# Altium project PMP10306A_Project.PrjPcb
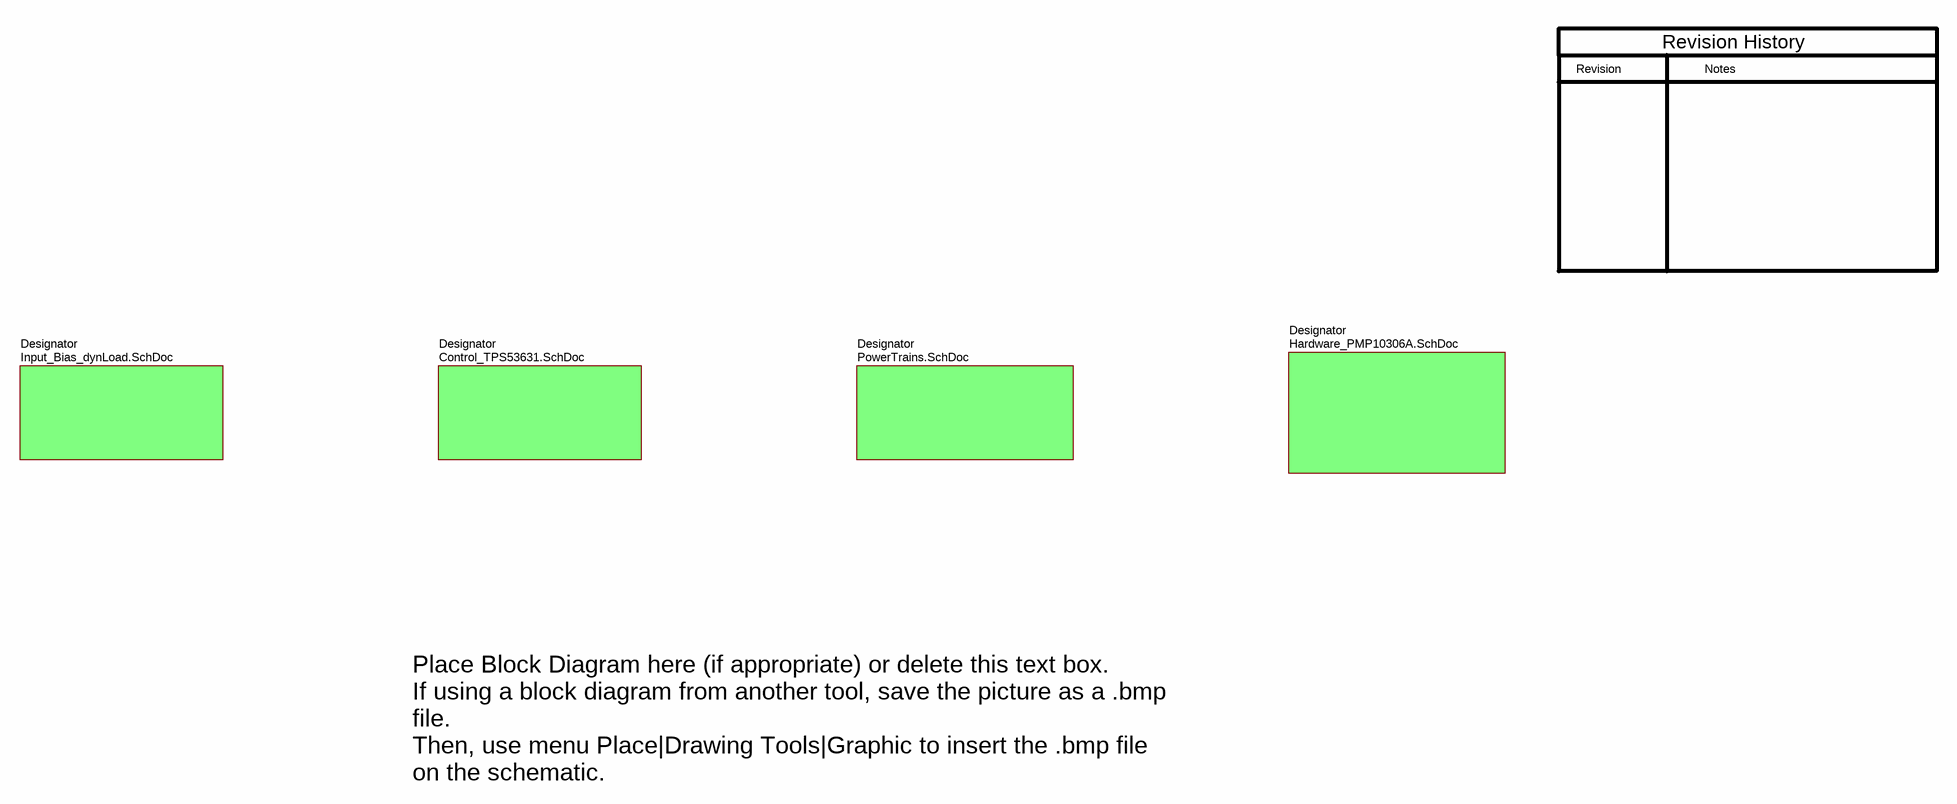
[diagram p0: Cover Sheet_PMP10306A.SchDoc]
TechSupport: http://www.ti.com/support; SCH_Rev: A; PRJ_Title: TPS53631 / CSD95378B(x3) for DDR4; PRJ_Number: PMP10306; PRJ_Engineer: Josh Mandelcorn; PRJ_Customer: Public Release; PCB_Rev: A; PCB_Layout: Use PMP9738A PCB; CopyrightYear: 2014
5 sheets, 207 parts. Net scope: flat (ports and power ports of the same name join across sheets).
Board file: PMP10306A.PcbDoc
Sheets:
  Cover Sheet_PMP10306A.SchDoc
    Designator = Input_Bias_dynLoad.SchDoc
    Designator = Control_TPS53631.SchDoc
    Designator = PowerTrains.SchDoc
    Designator = Hardware_PMP10306A.SchDoc

## Sheet Cover Sheet_PMP10306A.SchDoc
size 431 x 279 mm; Date: Not shown in title block; ApprovedBy: Not shown in title block; CheckedBy: Not shown in title block; Author: Not shown in title block; CompanyName: Not shown in title block; Engineer: Not shown in title block; Organization: Not shown in title block; Address1: Not shown in title block; Address2: Not shown in title block; Address3: Not shown in title block; Address4: Not shown in title block; DocumentNumber: 1; Revision: Use project parameter SCH_Rev; SheetNumber: 1; SheetTotal: 5; PageSetup: Record=PageOptions|CenterHorizontal=True|CenterVertical=True|PrintScale=1.00|XCorrection=1.00|YCorrection=1.00|PrintKind=0|BorderSize=5000000|LeftOffset=0|BottomOffset=0|Orientation=2|PaperLength=1000|PaperWidth=1000|Scale=100|PaperSource=15|PrintQuality=600|MediaType=1|DitherType=10|PaperKind=Letter|PrintScaleMode=1

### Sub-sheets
Designator = Input_Bias_dynLoad.SchDoc: no entries
Designator = Control_TPS53631.SchDoc: no entries
Designator = PowerTrains.SchDoc: no entries
Designator = Hardware_PMP10306A.SchDoc: no entries

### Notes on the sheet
- Revision
- Notes
- Revision History
- Place Block Diagram here (if appropriate) or delete this text box.
  If using a block diagram from another tool, save the picture as a .bmp file.
  Then, use menu Place|Drawing Tools|Graphic to insert the .bmp file on the schematic.

## Sheet Input_Bias_dynLoad.SchDoc
size 431 x 279 mm; Date: Not shown in title block; ApprovedBy: Not shown in title block; CheckedBy: Not shown in title block; Author: Not shown in title block; CompanyName: Not shown in title block; Engineer: Not shown in title block; Organization: Not shown in title block; Address1: Not shown in title block; Address2: Not shown in title block; Address3: Not shown in title block; Address4: Not shown in title block; DocumentNumber: 2; Revision: Use project parameter SCH_Rev; SheetNumber: 2; SheetTotal: 5; PageSetup: Record=PageOptions|CenterHorizontal=True|CenterVertical=True|PrintScale=1.00|XCorrection=1.00|YCorrection=1.00|PrintKind=0|BorderSize=5000000|LeftOffset=0|BottomOffset=0|Orientation=2|PaperLength=1000|PaperWidth=1000|Scale=100|PaperSource=15|PrintQuality=600|MediaType=1|DitherType=10|PaperKind=Letter|PrintScaleMode=1
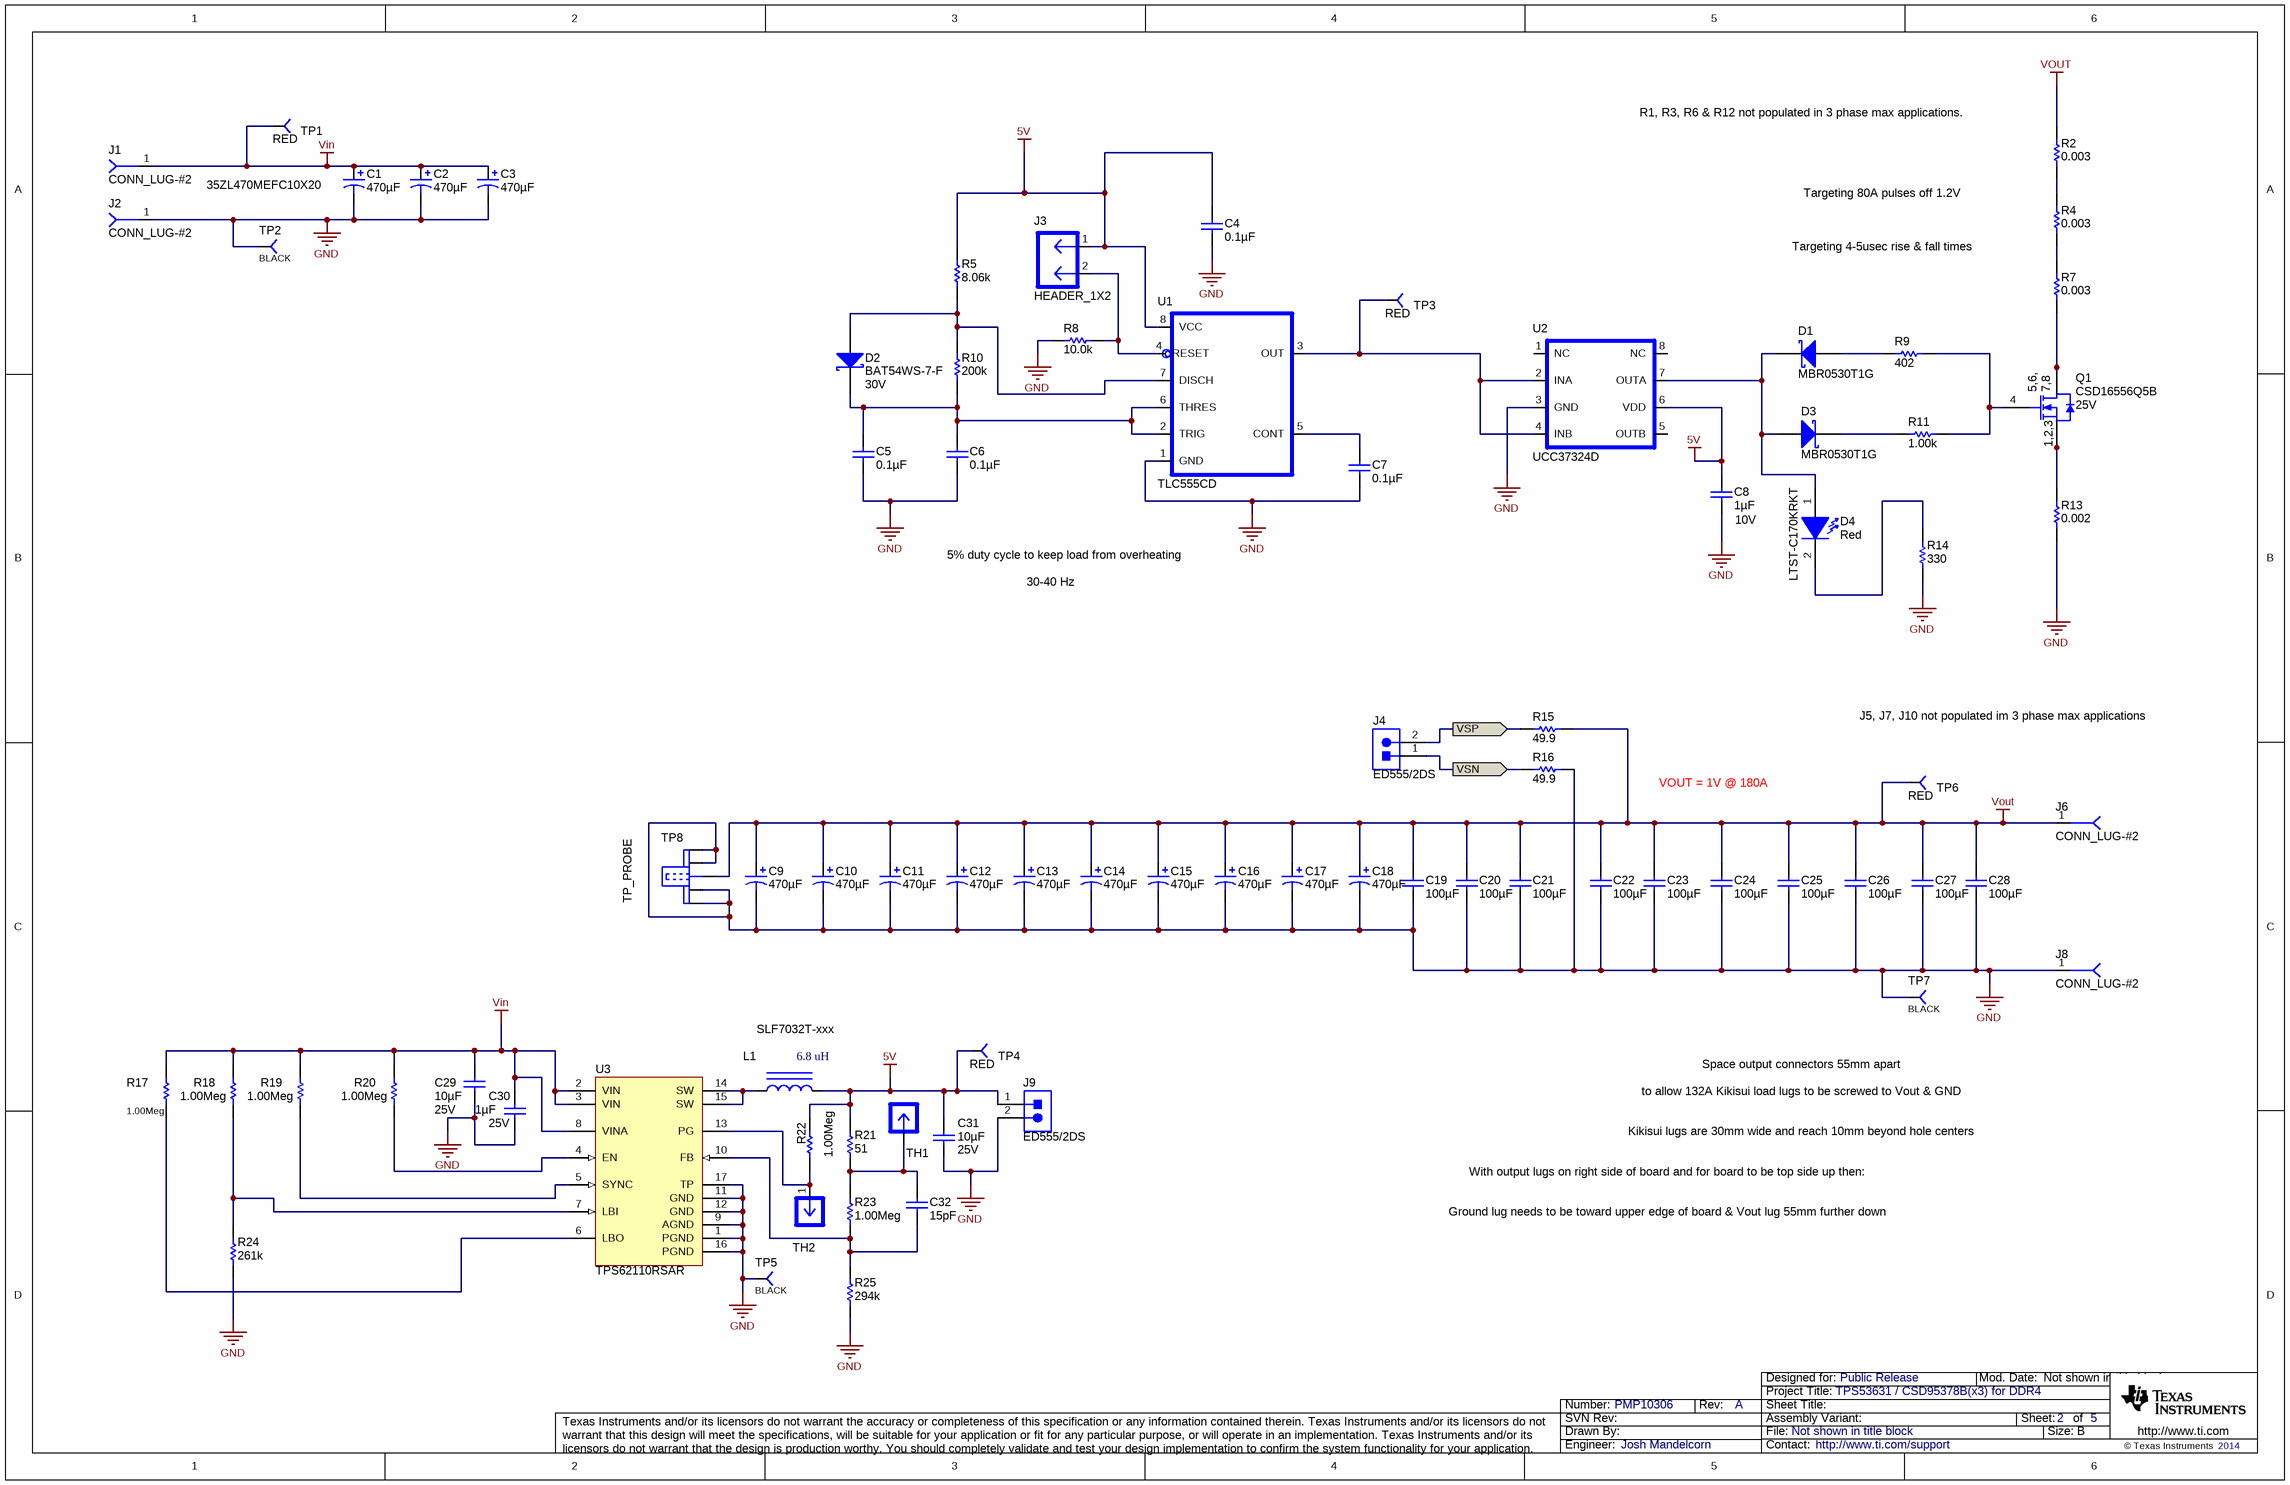
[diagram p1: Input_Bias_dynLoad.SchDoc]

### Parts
C1  ValueDisplayed: 470µF  [CAPPR5-10X20]  (hidden comment: 35ZL470MEFC10X20)
C2  ValueDisplayed: 470µF  [CAPPR5-10X20]  (hidden comment: 35ZL470MEFC10X20)
C3  ValueDisplayed: 470µF  [CAPPR5-10X20]  (hidden comment: 35ZL470MEFC10X20)
C4  ValueDisplayed: 0.1µF  [0402]  (hidden comment: C1005X7R1H104M)
C5  ValueDisplayed: 0.1µF  [0402]  (hidden comment: C1005X7R1H104M)
C6  ValueDisplayed: 0.1µF  [0402]  (hidden comment: C1005X7R1H104M)
C7  ValueDisplayed: 0.1µF  [0402]  (hidden comment: C1005X7R1H104M)
C8  ValueDisplayed: 1µF  Value2: 10V  [0402]  (hidden comment: GRM155R61A105KE15D)
C9  ValueDisplayed: 470µF  [CAPAE_SP-Cap_Standard]  (hidden comment: EEFSX0E471ER)
C10  ValueDisplayed: 470µF  [CAPAE_SP-Cap_Standard]  (hidden comment: EEFSX0E471ER)
C11  ValueDisplayed: 470µF  [CAPAE_SP-Cap_Standard]  (hidden comment: EEFSX0E471ER)
C12  ValueDisplayed: 470µF  [CAPAE_SP-Cap_Standard]  (hidden comment: EEFSX0E471ER)
C13  ValueDisplayed: 470µF  [CAPAE_SP-Cap_Standard]  (hidden comment: EEFSX0E471ER)
C14  ValueDisplayed: 470µF  [CAPAE_SP-Cap_Standard]  (hidden comment: EEFSX0E471ER)
C15  ValueDisplayed: 470µF  [CAPAE_SP-Cap_Standard]  (hidden comment: EEFSX0E471ER)
C16  ValueDisplayed: 470µF  [CAPAE_SP-Cap_Standard]  (hidden comment: EEFSX0E471ER)
C17  ValueDisplayed: 470µF  [CAPAE_SP-Cap_Standard]  (hidden comment: EEFSX0E471ER)
C18  ValueDisplayed: 470µF  [CAPAE_SP-Cap_Standard]  (hidden comment: EEFSX0E471ER)
C19  ValueDisplayed: 100µF  [1210]  (hidden comment: C1210C107M9PACTU)
C20  ValueDisplayed: 100µF  [1210]  (hidden comment: C1210C107M9PACTU)
C21  ValueDisplayed: 100µF  [1210]  (hidden comment: C1210C107M9PACTU)
C22  ValueDisplayed: 100µF  [1210]  (hidden comment: C1210C107M9PACTU)
C23  ValueDisplayed: 100µF  [1210]  (hidden comment: C1210C107M9PACTU)
C24  ValueDisplayed: 100µF  [1210]  (hidden comment: C1210C107M9PACTU)
C25  ValueDisplayed: 100µF  [1210]  (hidden comment: C1210C107M9PACTU)
C26  ValueDisplayed: 100µF  [1210]  (hidden comment: C1210C107M9PACTU)
C27  ValueDisplayed: 100µF  [1210]  (hidden comment: C1210C107M9PACTU)
C28  ValueDisplayed: 100µF  [1210]  (hidden comment: C1210C107M9PACTU)
C29  ValueDisplayed: 10µF  Value2: 25V  [1210]  (hidden comment: C3225X7R1E106M)
C30  ValueDisplayed: 1µF  Value2: 25V  [0603]  (hidden comment: GRM188R71E105KA12D)
C31  ValueDisplayed: 10µF  Value2: 25V  [1210]  (hidden comment: C3225X7R1E106M)
C32  ValueDisplayed: 15pF  [0402]  (hidden comment: GRM1555C1H150JA01D)
D1  MBR0530T1G  [SOD-123]
D2  BAT54WS-7-F  value 30V  [sod-323]
D3  MBR0530T1G  [SOD-123]
D4  LTST-C170KRKT  value Red  [LED_LTST-C170]
J1  CONN_LUG-#2  [LUG-#2]
J2  CONN_LUG-#2  [LUG-#2]
J3  HEADER_1X2  [HDR100_1X2]
J4  ED555/2DS  [TERM_BLK_ED555-2DS]
J6  CONN_LUG-#2  [LUG-#2]
J8  CONN_LUG-#2  [LUG-#2]
J9  ED555/2DS  [TERM_BLK_ED555-2DS]
L1  SLF7032T-xxx  value 6.8 uH  [IND_SLF7032]
Q1  CSD16556Q5B  value 25V  [TRANS_NexFET_Q5B]
R2  value 0.003  [2512M]  (hidden comment: 73M1R003F)
R4  value 0.003  [2512M]  (hidden comment: 73M1R003F)
R5  value 8.06k  [0402]  (hidden comment: CRCW04028K06FKED)
R7  value 0.003  [2512M]  (hidden comment: 73M1R003F)
R8  value 10.0k  [0402]  (hidden comment: CRCW040210K0FKED)
R9  value 402  [0402]  (hidden comment: CRCW0402402RFKED)
R10  value 200k  [0402]  (hidden comment: CRCW0402200KFKED)
R11  value 1.00k  [0402]  (hidden comment: CRCW04021K00FKED)
R13  value 0.002  [2512M]  (hidden comment: CSNL2512FT2L00)
R14  value 330  [0402]  (hidden comment: CRCW0402330RJNED)
R15  value 49.9  [0402]  (hidden comment: CRCW040249R9FKED)
R16  value 49.9  [0402]  (hidden comment: CRCW040249R9FKED)
R17  value 1.00Meg  [0402]  (hidden comment: CRCW04021M00FKED)
R18  value 1.00Meg  [0402]  (hidden comment: CRCW04021M00FKED)
R19  value 1.00Meg  [0402]  (hidden comment: CRCW04021M00FKED)
R20  value 1.00Meg  [0402]  (hidden comment: CRCW04021M00FKED)
R21  value 51  [0402]  (hidden comment: CRCW040251R0JNED)
R22  value 1.00Meg  [0402]  (hidden comment: CRCW04021M00FKED)
R23  value 1.00Meg  [0402]  (hidden comment: CRCW04021M00FKED)
R24  value 261k  [0402]  (hidden comment: CRCW0402261KFKED)
R25  value 294k  [0402]  (hidden comment: CRCW0402294KFKED)
TH1  TP-15MIL  [TH-15MIL]  (value not drawn)
TH2  TP-15MIL  [TH-15MIL]  (value not drawn)
TP1  RED  [TH-40]
TP2  BLACK  [TH-40]
TP3  RED  [TH-40]
TP4  RED  [TH-40]
TP5  BLACK  [TH-40]
TP6  RED  [TH-40]
TP7  BLACK  [TH-40]
TP8  TP_PROBE  [PROBE]
U1  TLC555CD  [SO8]
U2  UCC37324D  [SO8]
U3  TPS62110RSAR  [RSA0016B]

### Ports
VSN (out), VSP (out)

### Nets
5V: C4.1 C8.1 C31.1 J3.1 J9.1 L1.2 R5.2 R21.2 R22.2 TP4.1 U1.8(VCC) U2.6(VDD)
GND: C1.2(-) C2.2(-) C3.2(-) C4.2 C5.2 C6.2 C7.2 C8.2 C9.2(-) C10.2(-) C11.2(-) C12.2(-) C13.2(-) C14.2(-) C15.2(-) C16.2(-) C17.2(-) C18.2(-) C19.2 C20.2 C21.2 C22.2 C23.2 C24.2 C25.2 C26.2 C27.2 C28.2 C29.2 C30.2 C31.2 J2.1 J8.1 J9.2 R8.1 R13.1 R14.1 R16.2 R24.1 R25.1 TP2.1 TP5.1 TP7.1 TP8.2(GND) TP8.3(GND) TP8.4(GND) TP8.5(GND) U1.1(GND) U2.3(GND) U3.1(PGND) U3.9(AGND) U3.11(GND) U3.12(GND) U3.16(PGND) U3.17(TP)
Vin: C1.1(+) C2.1(+) C3.1(+) C29.1 C30.1 J1.1 R17.2 R18.2 R19.1 R20.2 TP1.1 U3.2(VIN) U3.3(VIN) U3.8(VINA)
VOUT: C9.1(+) C10.1(+) C11.1(+) C12.1(+) C13.1(+) C14.1(+) C15.1(+) C16.1(+) C17.1(+) C18.1(+) C19.1 C20.1 C21.1 C22.1 C23.1 C24.1 C25.1 C26.1 C27.1 C28.1 J6.1 R2.2 R15.2 TP6.1 TP8.1(SIGNAL)
VSN: J4.1 R16.1 ; port VSN
VSP: J4.2 R15.1 ; port VSP
NetC5_1: C5.1 C6.1 D2.1(K) R10.1 U1.2(TRIG) U1.6(THRES)
NetC7_1: C7.1 U1.5(CONT)
NetC32_1: C32.1 R21.1 R23.2 TH1.1
NetC32_2: C32.2 R23.1 R25.2 U3.10(FB)
NetD1_1: D1.1(K) D3.2(A) D4.1(A) U2.7(OUTA)
NetD1_2: D1.2(A) R9.1
NetD2_2: D2.2(A) R5.1 R10.2 U1.7(DISCH)
NetD3_1: D3.1(K) R11.1
NetD4_2: D4.2(K) R14.2
NetJ3_2: J3.2 R8.2 U1.4(RESET)
NetL1_1: L1.1 U3.14(SW) U3.15(SW)
NetQ1_1: Q1.1(S) Q1.2(S) Q1.3(S) R13.2
NetQ1_4: Q1.4(G) R9.2 R11.2
NetQ1_5: Q1.5(D) Q1.6(D) Q1.7(D) Q1.8(D) R7.1
NetR2_1: R2.1 R4.2
NetR4_1: R4.1 R7.2
NetR17_1: R17.1 U3.6(LBO)
NetR18_1: R18.1 R24.2 U3.7(LBI)
NetR19_2: R19.2 U3.5(SYNC)
NetR20_1: R20.1 U3.4(EN)
NetR22_1: R22.1 TH2.1 U3.13(PG)
NetTP3_1: TP3.1 U1.3(OUT) U2.2(INA) U2.4(INB)

Not connected (* = marked no-connect by the designer): U2 1(NC) 5(OUTB) 8(NC)

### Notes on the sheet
- R1, R3, R6 & R12 not populated in 3 phase max applications.
- Targeting 80A pulses off 1.2V
- Targeting 4-5usec rise & fall times
- 5% duty cycle to keep load from overheating
- 30-40 Hz
- J5, J7, J10 not populated im 3 phase max applications
- VOUT = 1V @ 180A
- Space output connectors 55mm apart
- to allow 132A Kikisui load lugs to be screwed to Vout & GND
- With output lugs on right side of board and for board to be top side up then:
- Kikisui lugs are 30mm wide and reach 10mm beyond hole centers
- Ground lug needs to be toward upper edge of board & Vout lug 55mm further down

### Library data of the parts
C1-C3 = 35ZL470MEFC10X20: CAP, AL, 470uF, 35V, +/-20%, TH; Manufacturer: Rubycon; Polarized: Y; CompType: Capacitor; U/M: EA; Cap_F: 0.00047; Tolerance_%: 20; Value1: Unknown; VDC_V: 35; TaMin_C: -40; TaMax_C: 105; Cap_Case: 10x20
C4-C7 = C1005X7R1H104M: CAP, CERM, 0.1uF, 50V, +/-20%, X7R, 0402; Manufacturer: TDK; Polarized: N; CompType: Capacitor; U/M: EA; Cap_F: 0.0000001; Tolerance_%: 20; Value1: Unknown; VDC_V: 50; TempCo: C0G/NP0; TaMin_C: -55; TaMax_C: 125
C8 = GRM155R61A105KE15D: CAP, CERM, 1uF, 10V, +/-10%, X5R, 0402; Manufacturer: MuRata; Polarized: N; CompType: Capacitor; U/M: EA; Cap_F: 0.000001; Tolerance_%: 10; Value1: Unknown; TaMin_C: -55; TaMax_C: 85
C9-C18 = EEFSX0E471ER: CAP, AL, 470uF, 2.5V, +/-20%, 9 ohm, SMD; Manufacturer: Panasonic; Polarized: Y; CompType: Capacitor; U/M: EA; Cap_F: 0.00047; Tolerance_%: 20; Value1: 9 ohm; VDC_V: 2.5; ESR_Ohm: 9; IRMS_A: 3; TaMin_C: -40; TaMax_C: 105
C19-C28 = C1210C107M9PACTU: CAP, CERM, 100uF, 6.3V, +/-20%, X5R, 1210; Manufacturer: Kemet; Polarized: N; CompType: Capacitor; U/M: EA; Cap_F: 0.0001; Tolerance_%: 20; Value1: Unknown; VDC_V: 6.3; TaMin_C: -55; TaMax_C: 85
C29 C31 = C3225X7R1E106M: CAP, CERM, 10uF, 25V, +/-20%, X7R, 1210; Manufacturer: TDK; Polarized: N; CompType: Capacitor; U/M: EA; Cap_F: 0.00001; Tolerance_%: 20; ESR_Ohm: 0.0027; Value1: 0.0027 ohm; VDC_V: 25; IRMS_A: 3; TaMin_C: -55; TaMax_C: 125
C30 = GRM188R71E105KA12D: CAP, CERM, 1uF, 25V, +/-10%, X7R, 0603; Manufacturer: MuRata; Polarized: N; CompType: Capacitor; U/M: EA; Cap_F: 0.000001; Tolerance_%: 10; Value1: Unknown; VDC_V: 25; TaMin_C: -55; TaMax_C: 125
C32 = GRM1555C1H150JA01D: CAP, CERM, 15pF, 50V, +/-5%, C0G/NP0, 0402; Manufacturer: MuRata; Polarized: N; CompType: Capacitor; U/M: EA; Cap_F: 0.000000000015; Tolerance_%: 5; Value1: Unknown; VDC_V: 50; TaMin_C: -55; TaMax_C: 125
D1 D3 = MBR0530T1G: Diode, Schottky, 30V, 0.5A, SOD-123; Manufacturer: ON Semiconductor; U/M: EA; Vf_V: 0.43; Value2: 0.43V; Io_A: 0.5; Vr_V: 30; TJmax_C: 125; RJC_CperW: 150
D2 = BAT54WS-7-F: Diode, Schottky, 30V, 0.2A, SOD-323; Manufacturer: Diodes Inc.; U/M: EA; Vf_V: 0.7; Value2: 0.7V; Io_A: 0.2; Vr_V: 30; TJmax_C: 125
D4 = LTST-C170KRKT: LED, Red, SMD; Manufacturer: Lite-On; Type: AlInGaP; Vf_V: 2; Value2: 2V; Io_A: 20; Value1: W; U/M: EA
J1 J2 J6 J8 = CONN_LUG-#2: Lug, Solderless, #2 - #8 AWG, 1/4", Copper; Manufacturer: ILSCO; PartNumber: GSLU-70; area: 960000; Value: GSLU-70
J3 = HEADER_1X2: Header, Male 2-pin, 100mil spacing,; Manufacturer: Sullins; PartNumber: PEC02SAAN; area: 20000; Value: PEC02SAAN
J4 J9 = ED555/2DS: Terminal Block, 6A, 3.5mm Pitch, 2-Pos, TH; Manufacturer: On-Shore Technology; SymbolCreator: a0412235; CompType: Connector; U/M: EA
L1 = IND_SLF7032T-XXX: Inductor, SMT, yyA, zzmilliohm; Manufacturer: TDK; Area: 114,138
Q1 = CSD16556Q5B: MOSFET, N-CH, 25V, 40A, SON 5x6mm; Manufacturer: Texas Instruments; Alternate Manufacturer: None; U/M: EA; ChType: N; VdsMax_V: 25; Value1: 0.0012 ohm; Rdson45_Ohm: 0.0012; Value2: 36 nC; QgTyp_nC: 36; Vgs_V: 20; IdsMax_A: 40
R2 R4 R7 = 73M1R003F: RES, 0.003 ohm, 1%, 1W, 2512; Manufacturer: CTS Resistor; CompType: Resistor; Value_Code: R003; Tolerance_%: 1; TempCo: 300 ppm/C; EIA_Code: E96; U/M: EA
R5 = CRCW04028K06FKED: RES, 8.06k ohm, 1%, 0.063W, 0402; Manufacturer: Vishay-Dale; CompType: Resistor; Res_ohm: 8060; Value_Code: 8k06; Tolerance_%: 1; Power_W: 0.063; VDC_V: 50; TempCo: 100 ppm/C; EIA_Code: E96; U/M: EA
R8 = CRCW040210K0FKED: RES, 10.0k ohm, 1%, 0.063W, 0402; Manufacturer: Vishay-Dale; CompType: Resistor; Res_ohm: 10000; Value_Code: 10k0; Tolerance_%: 1; Power_W: 0.063; VDC_V: 50; TempCo: 100 ppm/C; EIA_Code: E96; U/M: EA
R9 = CRCW0402402RFKED: RES, 402 ohm, 1%, 0.063W, 0402; Manufacturer: Vishay-Dale; CompType: Resistor; Value_Code: 402R; Tolerance_%: 1; Power_W: 0.063; VDC_V: 50; TempCo: 100 ppm/C; EIA_Code: E96; U/M: EA
R10 = CRCW0402200KFKED: RES, 200k ohm, 1%, 0.063W, 0402; Manufacturer: Vishay-Dale; CompType: Resistor; Res_ohm: 200000; Tolerance_%: 1; Power_W: 0.063; VDC_V: 50; TempCo: 100 ppm/C; EIA_Code: E96; U/M: EA
R11 = CRCW04021K00FKED: RES, 1.00k ohm, 1%, 0.063W, 0402; Manufacturer: Vishay-Dale; CompType: Resistor; Res_ohm: 1000; Value_Code: 1k00; Tolerance_%: 1; Power_W: 0.063; VDC_V: 50; TempCo: 100 ppm/C; EIA_Code: E96; U/M: EA
R13 = CSNL2512FT2L00: RES, 0.002 ohm, 1%, 2W, 2512; Manufacturer: Stackpole Electronics Inc; CompType: Resistor; Value_Code: R002; Tolerance_%: 1; Power_W: 2; VDC_V: 200; TempCo: 50 ppm/C; U/M: EA
R14 = CRCW0402330RJNED: RES, 330 ohm, 5%, 0.063W, 0402; Manufacturer: Vishay-Dale; CompType: Resistor; Value_Code: 330R; Tolerance_%: 5; Power_W: 0.063; VDC_V: 50; TempCo: 200 ppm/C; EIA_Code: E24; U/M: EA
R15 R16 = CRCW040249R9FKED: RES, 49.9 ohm, 1%, 0.063W, 0402; Manufacturer: Vishay-Dale; CompType: Resistor; Value_Code: 49R9; Tolerance_%: 1; Power_W: 0.063; VDC_V: 50; TempCo: 100 ppm/C; EIA_Code: E96; U/M: EA
R17-R20 R22 R23 = CRCW04021M00FKED: RES, 1.00Meg ohm, 1%, 0.063W, 0402; Manufacturer: Vishay-Dale; CompType: Resistor; Res_ohm: 1000000; Value_Code: 1M00; Tolerance_%: 1; Power_W: 0.063; VDC_V: 50; TempCo: 100 ppm/C; EIA_Code: E96; U/M: EA
R21 = CRCW040251R0JNED: RES, 51 ohm, 5%, 0.063W, 0402; Manufacturer: Vishay-Dale; CompType: Resistor; Value_Code: 51R0; Tolerance_%: 5; Power_W: 0.063; VDC_V: 50; TempCo: 200 ppm/C; EIA_Code: E24; U/M: EA
R24 = CRCW0402261KFKED: RES, 261k ohm, 1%, 0.063W, 0402; Manufacturer: Vishay-Dale; CompType: Resistor; Res_ohm: 261000; Tolerance_%: 1; Power_W: 0.063; VDC_V: 50; TempCo: 100 ppm/C; EIA_Code: E96; U/M: EA
R25 = CRCW0402294KFKED: RES, 294k ohm, 1%, 0.063W, 0402; Manufacturer: Vishay-Dale; CompType: Resistor; Res_ohm: 294000; Tolerance_%: 1; Power_W: 0.063; VDC_V: 50; TempCo: 100 ppm/C; EIA_Code: E96; U/M: EA
TH1 TH2 = TP-15MIL: Thru Hole, 15 mil, plated
TP1 TP3 TP4 TP6 = TP-5000-RED: Test Point,  Red, Thru Hole Color Keyed; Manufacturer: Keystone; PartNumber: 5000; area: 10.000; Value: 5000
TP2 TP5 TP7 = TP-5001-BLACK: Test Point,  Black, Thru Hole Color Keyed; Manufacturer: Keystone; PartNumber: 5001; area: 10.000; Value: 5001
TP8 = TP_PROBE: Adaptor, 3.5-mm probe clip (or 131-5031-00); Manufacturer: Tektronix; PartNumber: 131-4244-00; Value: 131-4244-00
U1 = TLC555CD: IC, Timer, Low-Power CMOS; Manufacturer: TI; Alternate Manufacturer: None; Area: 75900
U2 = UCC3732XD: IC, Dual  4-A High Speed Low-Side Power MOSFET Drivers; Manufacturer: TI; Alternate Manufacturer: None; Area: 75900
U3 = TPS62110RSAR: Buck Adjustable Regulator with 3.1 to 17 V Input and 1.2 to 16 V Output, -40 to 85 degC, 16-Pin QFN (RSA), Green (RoHS & no Sb/Br); Manufacturer: Texas Instruments; Alternate Manufacturer: None; Alternate PartNumber: Equivalent; Duty Cycle(Max)(%): 100; Iout(Max)(A): 1.5; Iq(Typ)(mA): 0.02; Rating: Catalog; Regulated Outputs(#): 1; SubFamily: Step-Down Regulator; Switch Current Limit(Typ)(A): 2.4; Synchronous Rectification: TRUE; Vin(Max)(V): 17; Vin(Min)(V): 3.1; Vout(Max)(V): 16; Vout(Min)(V): 1.2

## Sheet Control_TPS53631.SchDoc
size 431 x 279 mm; Date: Not shown in title block; ApprovedBy: Not shown in title block; CheckedBy: Not shown in title block; Author: Not shown in title block; CompanyName: Not shown in title block; Engineer: Not shown in title block; Organization: Not shown in title block; Address1: Not shown in title block; Address2: Not shown in title block; Address3: Not shown in title block; Address4: Not shown in title block; DocumentNumber: 3; Revision: Use project parameter SCH_Rev; SheetNumber: 3; SheetTotal: 5; PageSetup: Record=PageOptions|CenterHorizontal=True|CenterVertical=True|PrintScale=1.00|XCorrection=1.00|YCorrection=1.00|PrintKind=0|BorderSize=5000000|LeftOffset=0|BottomOffset=0|Orientation=2|PaperLength=1000|PaperWidth=1000|Scale=100|PaperSource=15|PrintQuality=600|MediaType=1|DitherType=10|PaperKind=Letter|PrintScaleMode=1
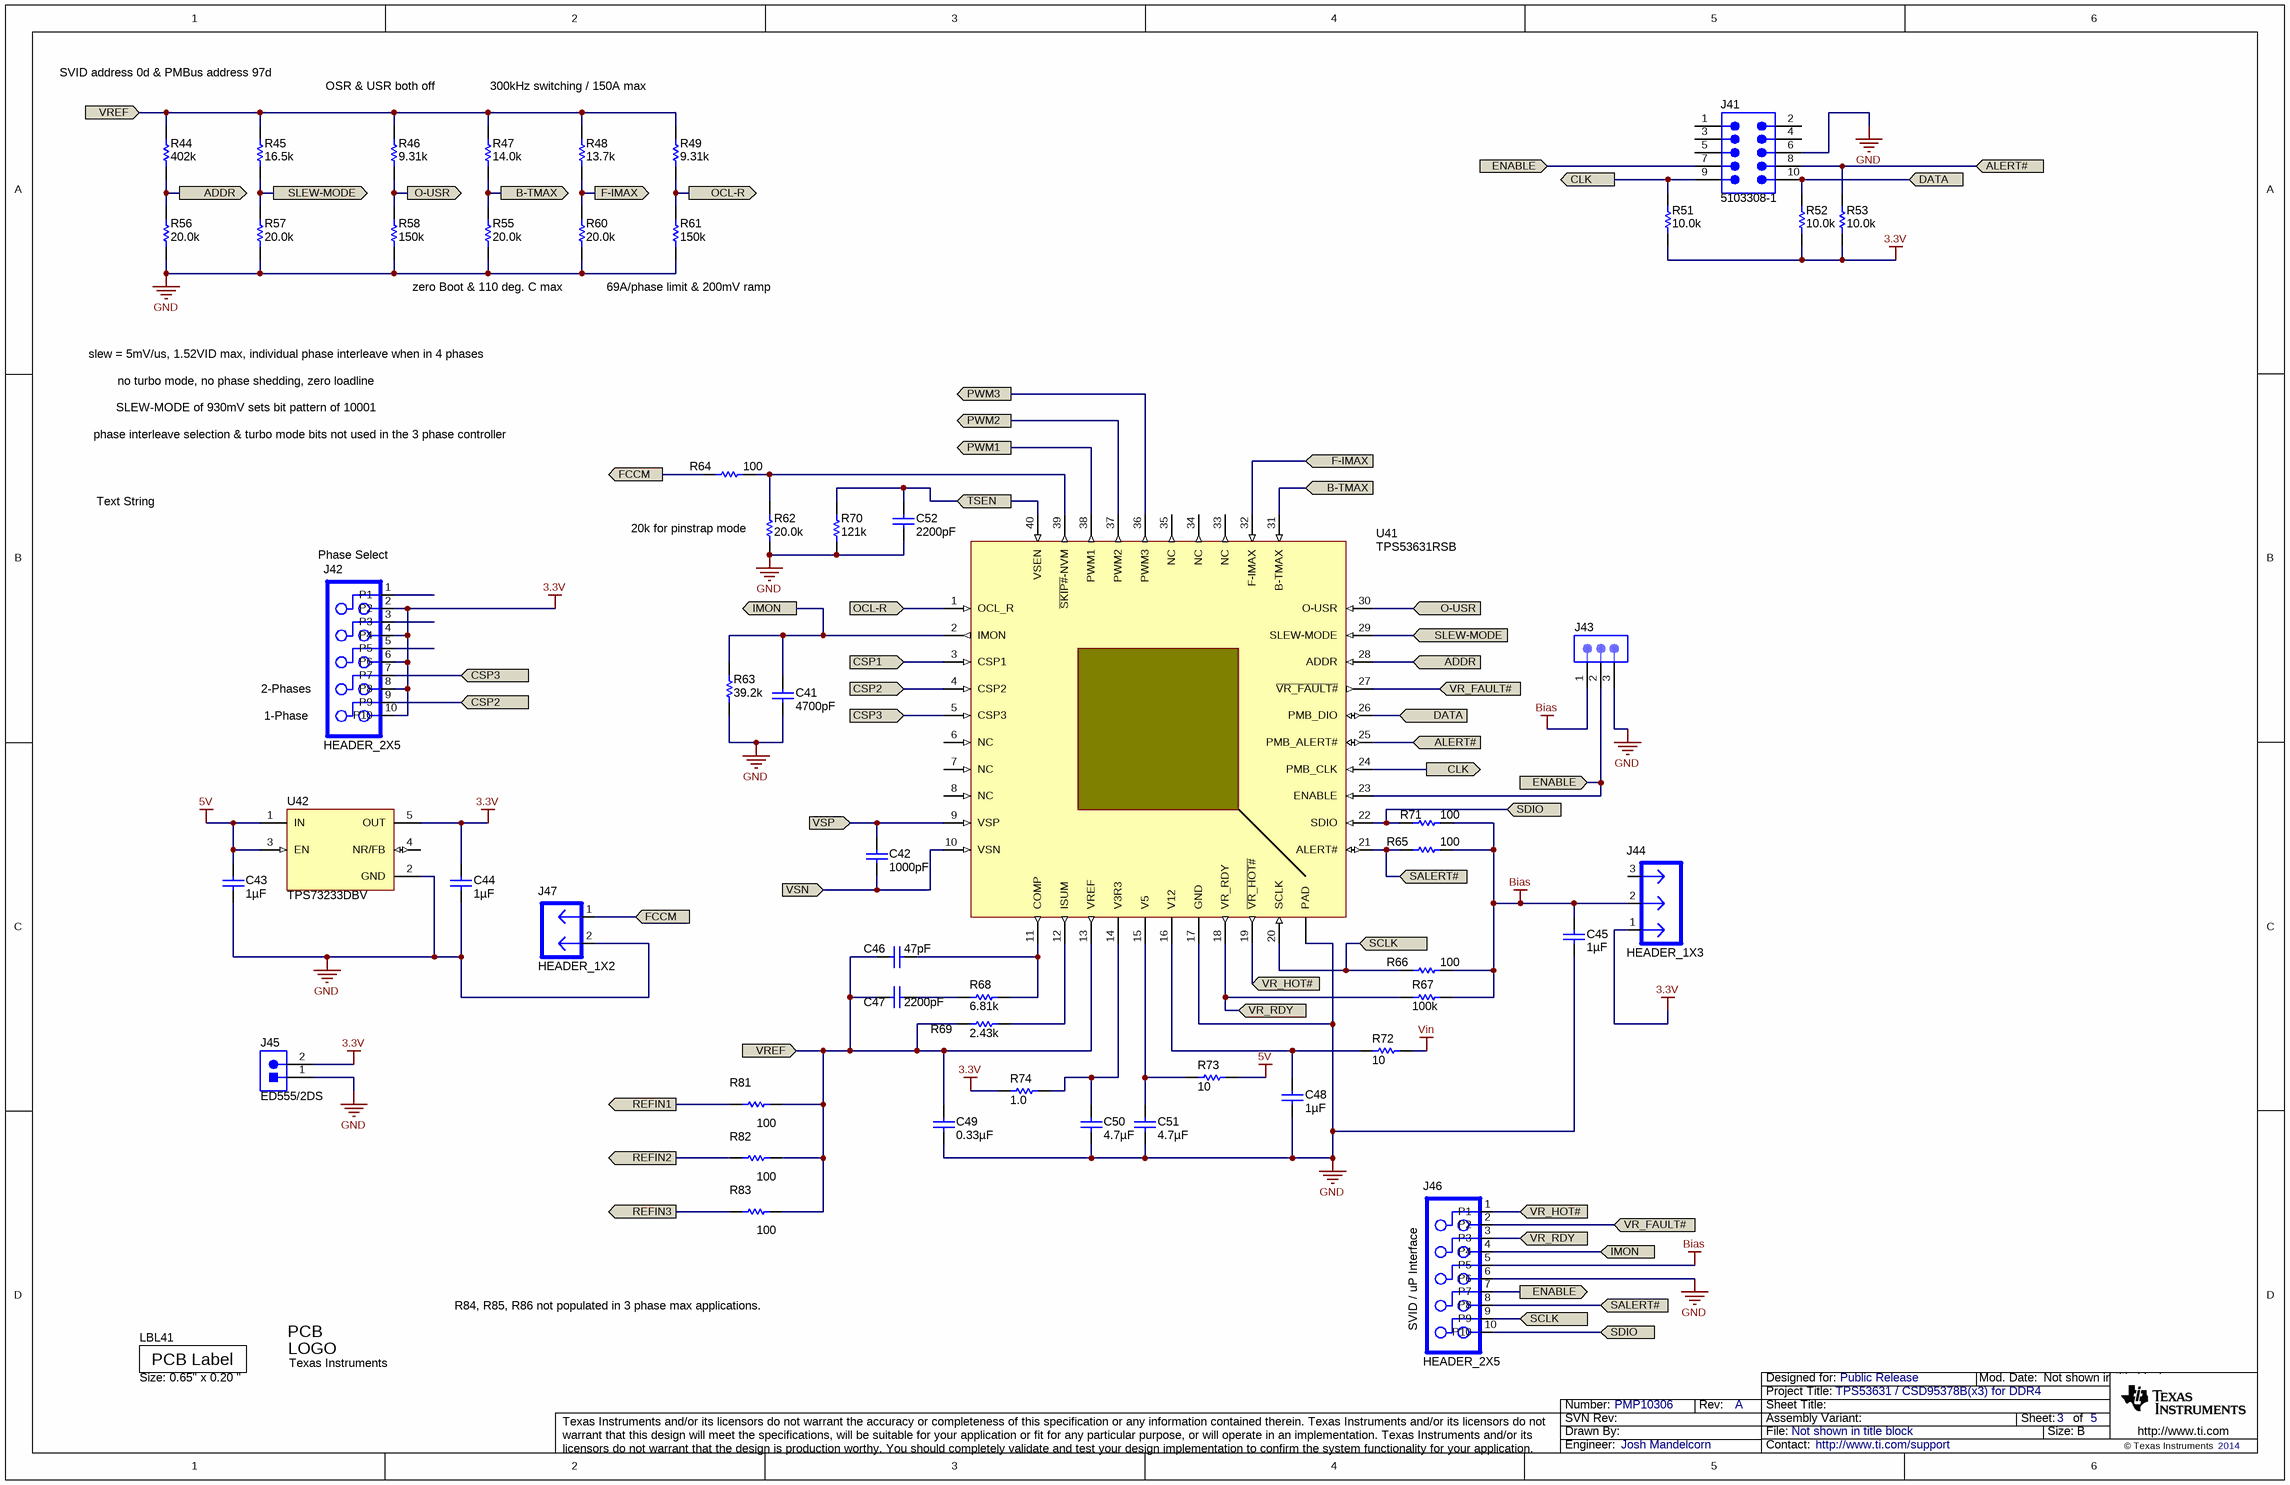
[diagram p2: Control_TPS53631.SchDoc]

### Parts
C41  ValueDisplayed: 4700pF  [0603]  (hidden comment: 06031C472KAT2A)
C42  ValueDisplayed: 1000pF  [0402]  (hidden comment: C1005X7R1H102K)
C43  ValueDisplayed: 1µF  [0603]  (hidden comment: C1608X5R1E105K080AC)
C44  ValueDisplayed: 1µF  [0603]  (hidden comment: C1608X5R1E105K080AC)
C45  ValueDisplayed: 1µF  [0603]  (hidden comment: C1608X5R1E105K080AC)
C46  ValueDisplayed: 47pF  [0402]  (hidden comment: GRM1555C1H470JA01D)
C47  ValueDisplayed: 2200pF  [0603]  (hidden comment: GRM188R71H222KA01D)
C48  ValueDisplayed: 1µF  [0603]  (hidden comment: C1608X5R1E105K080AC)
C49  ValueDisplayed: 0.33µF  [0402]  (hidden comment: GRM155R60J334KE01D)
C50  ValueDisplayed: 4.7µF  [0402]  (hidden comment: GRM155R61A475M)
C51  ValueDisplayed: 4.7µF  [0402]  (hidden comment: GRM155R61A475M)
C52  ValueDisplayed: 2200pF  [0402]  (hidden comment: C1005X7R1H222K)
J41  5103308-1  [CONN_5103308-1]
J42  HEADER_2X5  [HEADER_2X5]
J43  PBC03SAAN  [PBC03SAAN]  (value not drawn)
J44  HEADER_1X3  [HDR100_1X3]
J45  ED555/2DS  [TERM_BLK_ED555-2DS]
J46  HEADER_2X5  [HEADER_2X5]
J47  HEADER_1X2  [HDR100_1X2]
LBL41  Size: 0.65" x 0.20 "  [Label_650x200]
Logo41  Texas Instruments  [TI_Stacked_Overlay_Medium]  (no BOM)
R44  value 402k  [0402]  (hidden comment: CRCW0402402KFKED)
R45  value 16.5k  [0402]  (hidden comment: CRCW040216K5FKED)
R46  value 9.31k  [0402]  (hidden comment: CRCW04029K31FKED)
R47  value 14.0k  [0402]  (hidden comment: CRCW040214K0FKED)
R48  value 13.7k  [0402]  (hidden comment: CRCW040213K7FKED)
R49  value 9.31k  [0402]  (hidden comment: CRCW04029K31FKED)
R51  value 10.0k  [0402]  (hidden comment: CRCW040210K0FKED)
R52  value 10.0k  [0402]  (hidden comment: CRCW040210K0FKED)
R53  value 10.0k  [0402]  (hidden comment: CRCW040210K0FKED)
R55  value 20.0k  [0402]  (hidden comment: CRCW040220K0FKED)
R56  value 20.0k  [0402]  (hidden comment: CRCW040220K0FKED)
R57  value 20.0k  [0402]  (hidden comment: CRCW040220K0FKED)
R58  value 150k  [0402]  (hidden comment: CRCW0402150KFKED)
R60  value 20.0k  [0402]  (hidden comment: CRCW040220K0FKED)
R61  value 150k  [0402]  (hidden comment: CRCW0402150KFKED)
R62  value 20.0k  [0402]  (hidden comment: CRCW040220K0FKED)
R63  value 39.2k  [0402]  (hidden comment: CRCW040239K2FKED)
R64  value 100  [0402]  (hidden comment: CRCW0402100RJNED)
R65  value 100  [0402]  (hidden comment: CRCW0402100RJNED)
R66  value 100  [0402]  (hidden comment: CRCW0402100RJNED)
R67  value 100k  [0402]  (hidden comment: CRCW0402100KFKED)
R68  value 6.81k  [0402]  (hidden comment: CRCW04026K81FKED)
R69  value 2.43k  [0402]  (hidden comment: CRCW04022K43FKED)
R70  value 121k  [0402]  (hidden comment: CRCW0402121KFKED)
R71  value 100  [0402]  (hidden comment: CRCW0402100RJNED)
R72  value 10  [0402]  (hidden comment: CRCW040210R0JNED)
R73  value 10  [0402]  (hidden comment: CRCW040210R0JNED)
R74  value 1.0  [0402]  (hidden comment: CRCW04021R00JNED)
R81  value 100  [0402]  (hidden comment: CRCW0402100RJNED)
R82  value 100  [0402]  (hidden comment: CRCW0402100RJNED)
R83  value 100  [0402]  (hidden comment: CRCW0402100RJNED)
U41  TPS53631RSB  [RSB0040E]
U42  TPS73233DBV  [DBV0005A_N]

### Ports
ADDR (in), ADDR (out), ALERT#, ALERT# (in), B-TMAX (in), B-TMAX (out), CLK, CSP1 (in), CSP2, CSP2 (in), CSP3, CSP3 (in), DATA, DATA (in), ENABLE, F-IMAX (in), F-IMAX (out), FCCM, IMON, O-USR (in), O-USR (out), OCL-R (in), OCL-R (out), PWM1 (out), PWM2 (out), PWM3 (out), REFIN1 (out), REFIN2 (out), REFIN3 (out), SALERT#, SCLK, SDIO, SLEW-MODE (in), SLEW-MODE (out), TSEN, VR_FAULT#, VR_HOT#, VR_RDY, VREF, VSN (in), VSP (in)

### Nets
3.3V: C44.2 J42.2(P2) J42.4(P4) J42.6(P6) J42.8(P8) J42.10(P10) J44.1 J45.2 R51.2 R52.2 R53.2 R74.1 U42.5(OUT)
5V: C43.2 R73.2 U42.1(IN) U42.3(EN)
Bias: C45.1 J43.1 J44.2 J46.5(P5) R65.1 R66.1 R67.1 R71.1
GND: C41.2 C43.1 C44.1 C45.2 C48.2 C49.2 C50.2 C51.2 C52.2 J41.6 J43.3 J45.1 J46.6(P6) J47.2 R55.1 R56.1 R57.1 R58.1 R60.1 R61.1 R62.1 R63.1 R70.1 U41.17(GND) U41.41(PAD) U42.2(GND)
Vin: R72.2
ADDR: R44.1 R56.2 U41.28(ADDR) ; port ADDR
ALERT#: J41.8 R53.1 U41.25(PMB_ALERT#) ; port ALERT#
B-TMAX: R47.1 R55.2 U41.31(B-TMAX) ; port B-TMAX
CLK: J41.9 R51.1 U41.24(PMB_CLK) ; port CLK
CSP1: U41.3(CSP1) ; port CSP1
CSP2: J42.9(P9) U41.4(CSP2) ; port CSP2
CSP3: J42.7(P7) U41.5(CSP3) ; port CSP3
DATA: J41.10 R52.1 U41.26(PMB_DIO) ; port DATA
ENABLE: J41.7 J43.2 J46.7(P7) U41.23(ENABLE) ; port ENABLE
F-IMAX: R48.1 R60.2 U41.32(F-IMAX) ; port F-IMAX
FCCM: J47.1 R64.2 ; port FCCM
IMON: C41.1 J46.4(P4) R63.2 U41.2(IMON) ; port IMON
O-USR: R46.1 R58.2 U41.30(O-USR) ; port O-USR
OCL-R: R49.1 R61.2 U41.1(OCL_R) ; port OCL-R
PWM1: U41.38(PWM1) ; port PWM1
PWM2: U41.37(PWM2) ; port PWM2
PWM3: U41.36(PWM3) ; port PWM3
REFIN1: R81.2 ; port REFIN1
REFIN2: R82.2 ; port REFIN2
REFIN3: R83.2 ; port REFIN3
SALERT#: J46.8(P8) R65.2 U41.21(ALERT#) ; port SALERT#
SCLK: J46.9(P9) R66.2 U41.20(SCLK) ; port SCLK
SDIO: J46.10(P10) R71.2 U41.22(SDIO) ; port SDIO
SLEW-MODE: R45.1 R57.2 U41.29(SLEW-MODE) ; port SLEW-MODE
TSEN: C52.1 R70.2 U41.40(VSEN) ; port TSEN
VR_FAULT#: J46.2(P2) U41.27(~{VR_FAULT#}) ; port VR_FAULT#
VR_HOT#: J46.1(P1) U41.19(~{VR_HOT#}) ; port VR_HOT#
VR_RDY: J46.3(P3) R67.2 U41.18(VR_RDY) ; port VR_RDY
VREF: C46.1 C47.1 C49.1 R44.2 R45.2 R46.2 R47.2 R48.2 R49.2 R69.1 R81.1 R82.1 R83.1 U41.13(VREF) ; port VREF
VSN: C42.2 U41.10(VSN) ; port VSN
VSP: C42.1 U41.9(VSP) ; port VSP
NetC46_2: C46.2 R68.1 U41.11(COMP)
NetC47_2: C47.2 R68.2
NetC48_1: C48.1 R72.1 U41.16(V12)
NetC50_1: C50.1 R74.2 U41.14(V3R3)
NetC51_1: C51.1 R73.1 U41.15(V5)
NetR62_2: R62.2 R64.1 U41.39(~{SKIP#}-NVM)
NetR69_2: R69.2 U41.12(ISUM)

Not connected (* = marked no-connect by the designer): J41 1 2 3 4 5; J42 1(P1) 3(P3) 5(P5); J44 3; U41 6(NC) 7(NC) 8(NC) 33(NC) 34(NC) 35(NC); U42 4(NR/FB)

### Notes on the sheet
- SVID address 0d & PMBus address 97d
- OSR & USR both off
- 300kHz switching / 150A max
- zero Boot & 110 deg. C max
- 69A/phase limit & 200mV ramp
- slew = 5mV/us, 1.52VID max, individual phase interleave when in 4 phases
- no turbo mode, no phase shedding, zero loadline
- SLEW-MODE of 930mV sets bit pattern of 10001
- phase interleave selection & turbo mode bits not used in the 3 phase controller
- Text String
- (near J42) Phase Select
- (near R62) 20k for pinstrap mode
- 2-Phases
- 1-Phase
- R84, R85, R86 not populated in 3 phase max applications.
- SVID / uP Interface

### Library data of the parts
C41 = 06031C472KAT2A: CAP, CERM, 4700pF, 100V, +/-10%, X7R, 0603; Manufacturer: AVX; Polarized: N; CompType: Capacitor; U/M: EA; Cap_F: 0.0000000047; Tolerance_%: 10; ESR_Ohm: 0.136; Value1: 0.136 ohm; VDC_V: 100; TaMin_C: -55; TaMax_C: 125
C42 = C1005X7R1H102K: CAP, CERM, 1000pF, 50V, +/-10%, X7R, 0402; Manufacturer: TDK; Polarized: N; CompType: Capacitor; U/M: EA; Cap_F: 0.000000001; Tolerance_%: 10; ESR_Ohm: 0.2381; Value1: 0.2381 ohm; VDC_V: 50; TaMin_C: -55; TaMax_C: 125
C43-C45 C48 = C1608X5R1E105K080AC: CAP, CERM, 1uF, 25V, +/-10%, X5R, 0603; Manufacturer: TDK; Polarized: N; CompType: Capacitor; U/M: EA; Cap_F: 0.000001; Tolerance_%: 10; Value1: Unknown; VDC_V: 25; TaMin_C: -55; TaMax_C: 85
C46 = GRM1555C1H470JA01D: CAP, CERM, 47pF, 50V, +/-5%, C0G/NP0, 0402; Manufacturer: MuRata; Polarized: N; CompType: Capacitor; U/M: EA; Cap_F: 0.000000000047; Tolerance_%: 5; Value1: Unknown; VDC_V: 50; TaMin_C: -55; TaMax_C: 125
C47 = GRM188R71H222KA01D: CAP, CERM, 2200pF, 50V, +/-10%, X7R, 0603; Manufacturer: MuRata; Polarized: N; CompType: Capacitor; U/M: EA; Cap_F: 0.0000000022; Tolerance_%: 10; Value1: Unknown; VDC_V: 50; TaMin_C: -55; TaMax_C: 125
C49 = GRM155R60J334KE01D: CAP, CERM, 0.33uF, 6.3V, +/-10%, X5R, 0402; Manufacturer: MuRata; Polarized: N; CompType: Capacitor; U/M: EA; Cap_F: 0.00000033; Tolerance_%: 10; Value1: Unknown; VDC_V: 6.3; TaMin_C: -55; TaMax_C: 85
C50 C51 = GRM155R61A475M: CAP, CERM, 4.7uF, 10V, +/-20%, X5R, 0402; Manufacturer: MuRata; Polarized: N; CompType: Capacitor; U/M: EA; Cap_F: 0.0000047; Tolerance_%: 20; Value1: Unknown; VDC_V: 10; TaMin_C: -55; TaMax_C: 85
C52 = C1005X7R1H222K: CAP, CERM, 2200pF, 50V, +/-10%, X7R, 0402; Manufacturer: TDK; Polarized: N; CompType: Capacitor; U/M: EA; Cap_F: 0.0000000022; Tolerance_%: 10; ESR_Ohm: 0.1433; Value1: 0.1433 ohm; VDC_V: 50; TaMin_C: -55; TaMax_C: 125
J41 = 5103308-1: Header (shrouded), 100mil, 5x2, Gold, TH; Manufacturer: TE Connectivity; SymbolCreator: a0412235; CompType: Connector; U/M: EA
J42 J46 = HEADER_2X5: Header, Male 2x5-pin, 100mil spacing; Manufacturer: Sullins; PartNumber: PEC05DAAN; area: 100000; Value: PEC05DAAN
J43 = PBC03SAAN: Header, TH, 100mil, 1x3, Gold plated, 230 mil above insulator; Manufacturer: Sullins Connector Solutions; U/M: EA
J44 = HEADER_1X3: Header, Male 3-pin, 100mil spacing,; Manufacturer: Sullins; PartNumber: PEC03SAAN; area: 30000; Value: PEC03SAAN
J45 = ED555/2DS: as J4 on sheet Input_Bias_dynLoad
J47 = HEADER_1X2: as J3 on sheet Input_Bias_dynLoad
LBL41 = THT-14-423-10: Thermal Transfer Printable Labels, 0.650" W x 0.200" H - 10,000 per roll; Manufacturer: Brady; SymbolCreator: a0412235; CompType: Label
Logo41 = TI_Logo: Texas Instrument Corporate Signature; SymbolCreator: a0412235
R44 = CRCW0402402KFKED: RES, 402k ohm, 1%, 0.063W, 0402; Manufacturer: Vishay-Dale; CompType: Resistor; Res_ohm: 402000; Tolerance_%: 1; Power_W: 0.063; VDC_V: 50; TempCo: 100 ppm/C; EIA_Code: E96; U/M: EA
R45 = CRCW040216K5FKED: RES, 16.5k ohm, 1%, 0.063W, 0402; Manufacturer: Vishay-Dale; CompType: Resistor; Res_ohm: 16500; Value_Code: 16k5; Tolerance_%: 1; Power_W: 0.063; VDC_V: 50; TempCo: 100 ppm/C; EIA_Code: E96; U/M: EA
R46 R49 = CRCW04029K31FKED: RES, 9.31k ohm, 1%, 0.063W, 0402; Manufacturer: Vishay-Dale; CompType: Resistor; Res_ohm: 9310; Value_Code: 9k31; Tolerance_%: 1; Power_W: 0.063; VDC_V: 50; TempCo: 100 ppm/C; EIA_Code: E96; U/M: EA
R47 = CRCW040214K0FKED: RES, 14.0k ohm, 1%, 0.063W, 0402; Manufacturer: Vishay-Dale; CompType: Resistor; Res_ohm: 14000; Value_Code: 14k0; Tolerance_%: 1; Power_W: 0.063; VDC_V: 50; TempCo: 100 ppm/C; EIA_Code: E96; U/M: EA
R48 = CRCW040213K7FKED: RES, 13.7k ohm, 1%, 0.063W, 0402; Manufacturer: Vishay-Dale; CompType: Resistor; Res_ohm: 13700; Value_Code: 13k7; Tolerance_%: 1; Power_W: 0.063; VDC_V: 50; TempCo: 100 ppm/C; EIA_Code: E96; U/M: EA
R51-R53 = CRCW040210K0FKED: as R8 on sheet Input_Bias_dynLoad
R55-R57 R60 R62 = CRCW040220K0FKED: RES, 20.0k ohm, 1%, 0.063W, 0402; Manufacturer: Vishay-Dale; CompType: Resistor; Res_ohm: 20000; Value_Code: 20k0; Tolerance_%: 1; Power_W: 0.063; VDC_V: 50; TempCo: 100 ppm/C; EIA_Code: E96; U/M: EA
R58 R61 = CRCW0402150KFKED: RES, 150k ohm, 1%, 0.063W, 0402; Manufacturer: Vishay-Dale; CompType: Resistor; Res_ohm: 150000; Tolerance_%: 1; Power_W: 0.063; VDC_V: 50; TempCo: 100 ppm/C; EIA_Code: E96; U/M: EA
R63 = CRCW040239K2FKED: RES, 39.2k ohm, 1%, 0.063W, 0402; Manufacturer: Vishay-Dale; CompType: Resistor; Res_ohm: 39200; Value_Code: 39k2; Tolerance_%: 1; Power_W: 0.063; VDC_V: 50; TempCo: 100 ppm/C; EIA_Code: E96; U/M: EA
R64-R66 R71 R81-R83 = CRCW0402100RJNED: RES, 100 ohm, 5%, 0.063W, 0402; Manufacturer: Vishay-Dale; CompType: Resistor; Value_Code: 100R; Tolerance_%: 5; Power_W: 0.063; VDC_V: 50; TempCo: 200 ppm/C; EIA_Code: E24; U/M: EA
R67 = CRCW0402100KFKED: RES, 100k ohm, 1%, 0.063W, 0402; Manufacturer: Vishay-Dale; CompType: Resistor; Res_ohm: 100000; Tolerance_%: 1; Power_W: 0.063; VDC_V: 50; TempCo: 100 ppm/C; EIA_Code: E96; U/M: EA
R68 = CRCW04026K81FKED: RES, 6.81k ohm, 1%, 0.063W, 0402; Manufacturer: Vishay-Dale; CompType: Resistor; Res_ohm: 6810; Value_Code: 6k81; Tolerance_%: 1; Power_W: 0.063; VDC_V: 50; TempCo: 100 ppm/C; EIA_Code: E96; U/M: EA
R69 = CRCW04022K43FKED: RES, 2.43k ohm, 1%, 0.063W, 0402; Manufacturer: Vishay-Dale; CompType: Resistor; Res_ohm: 2430; Value_Code: 2k43; Tolerance_%: 1; Power_W: 0.063; VDC_V: 50; TempCo: 100 ppm/C; EIA_Code: E96; U/M: EA
R70 = CRCW0402121KFKED: RES, 121k ohm, 1%, 0.063W, 0402; Manufacturer: Vishay-Dale; CompType: Resistor; Res_ohm: 121000; Tolerance_%: 1; Power_W: 0.063; VDC_V: 50; TempCo: 100 ppm/C; EIA_Code: E96; U/M: EA
R72 R73 = CRCW040210R0JNED: RES, 10 ohm, 5%, 0.063W, 0402; Manufacturer: Vishay-Dale; CompType: Resistor; Value_Code: 10R0; Tolerance_%: 5; Power_W: 0.063; VDC_V: 50; TempCo: 200 ppm/C; EIA_Code: E24; U/M: EA
R74 = CRCW04021R00JNED: RES, 1.0 ohm, 5%, 0.063W, 0402; Manufacturer: Vishay-Dale; CompType: Resistor; Res_ohm: 1; Value_Code: 1R00; Tolerance_%: 5; Power_W: 0.063; VDC_V: 50; TempCo: 200 ppm/C; EIA_Code: E24; U/M: EA
U41 = TPS53661RSB: 3-Phase, D-CAP+ Step-Down VR12.x Server CPU VCORE and DDR Memory Controller with PMBus Interface, RSB0040E; Alternate Manufacturer: None; Manufacturer: Texas Instruments; SymbolCreator: a0799628; CompType: IC; U/M: EA
U42 = TPS73233DBV: Cap-Free, NMOS, 250mA Low Dropout Regulator with Reverse Current Protection, DBV0005A; Alternate Manufacturer: None; Manufacturer: Texas Instruments; SymbolCreator: a0411947; CompType: IC; U/M: EA

## Sheet PowerTrains.SchDoc
size 431 x 279 mm; Date: Not shown in title block; ApprovedBy: Not shown in title block; CheckedBy: Not shown in title block; Author: Not shown in title block; CompanyName: Not shown in title block; Engineer: Not shown in title block; Organization: Not shown in title block; Address1: Not shown in title block; Address2: Not shown in title block; Address3: Not shown in title block; Address4: Not shown in title block; DocumentNumber: 4; Revision: Use project parameter SCH_Rev; SheetNumber: 4; SheetTotal: 5; PageSetup: Record=PageOptions|CenterHorizontal=True|CenterVertical=True|PrintScale=1.00|XCorrection=1.00|YCorrection=1.00|PrintKind=0|BorderSize=5000000|LeftOffset=0|BottomOffset=0|Orientation=2|PaperLength=1000|PaperWidth=1000|Scale=100|PaperSource=15|PrintQuality=600|MediaType=1|DitherType=10|PaperKind=Letter|PrintScaleMode=1
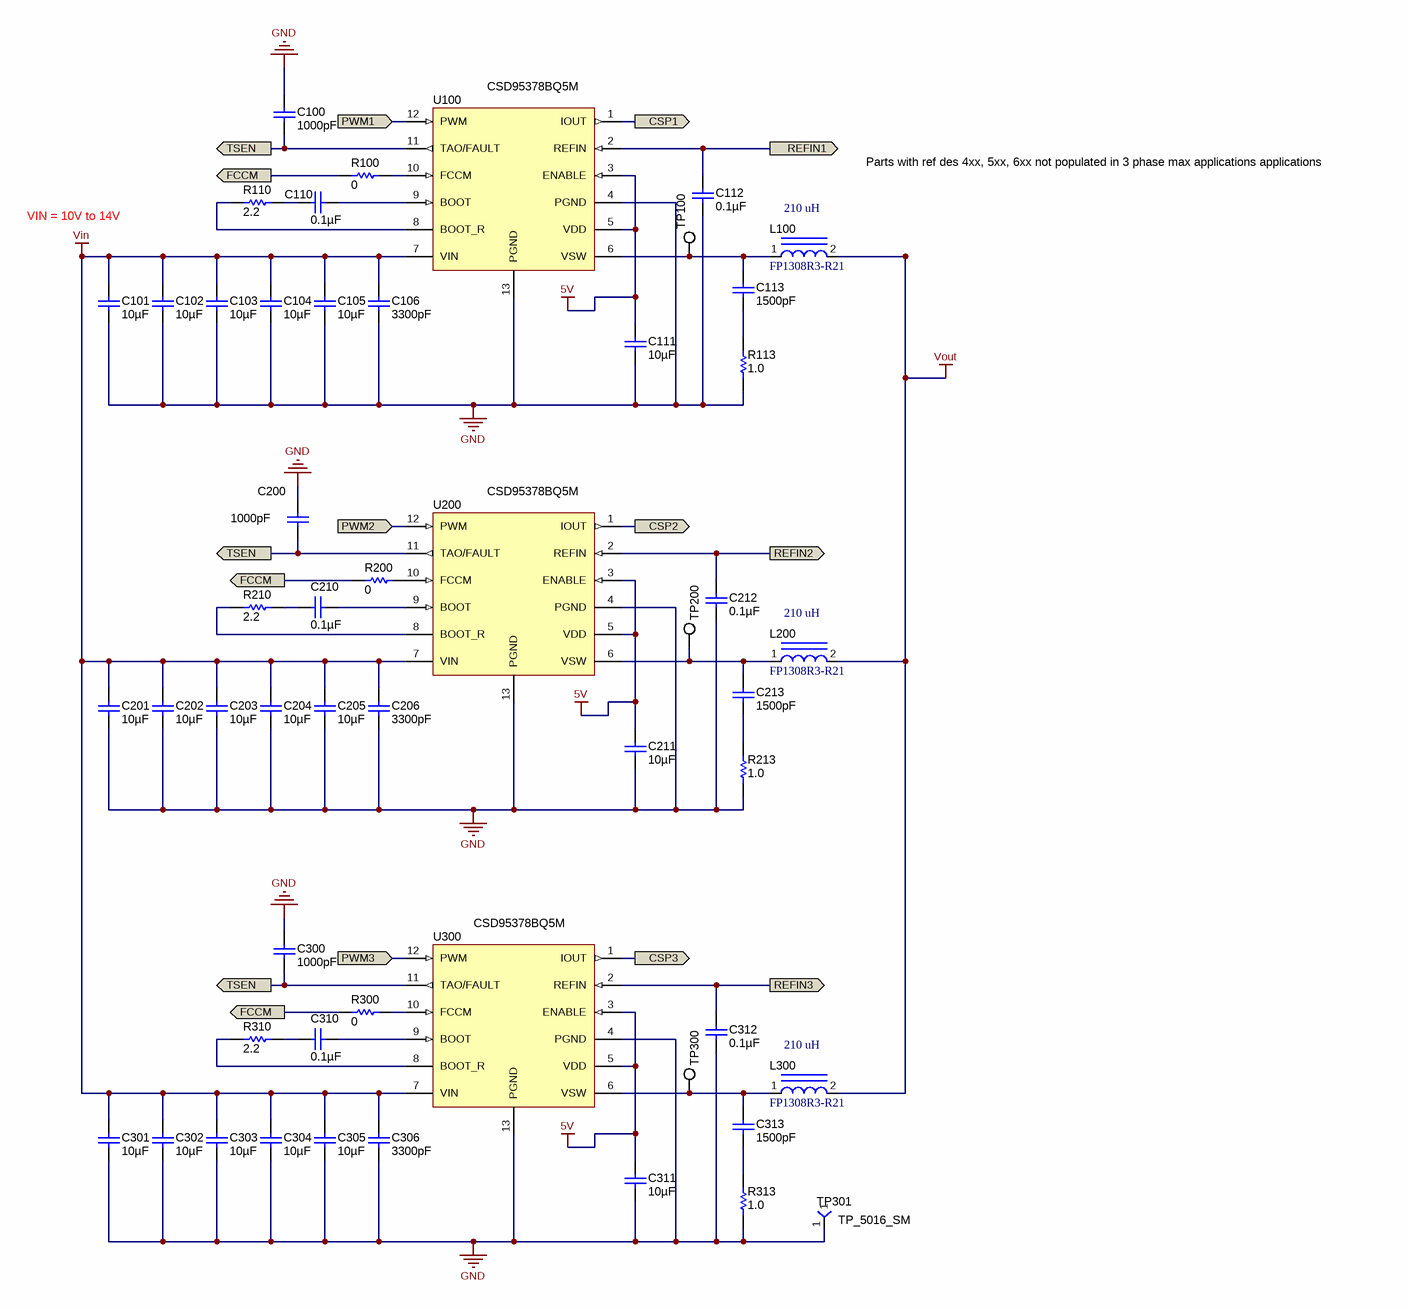
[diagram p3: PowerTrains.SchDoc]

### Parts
C100  ValueDisplayed: 1000pF  [0402]  (hidden comment: C1005C0G1E102J)
C101  ValueDisplayed: 10µF  [1206]  (hidden comment: GRM31CR71E106KA12L)
C102  ValueDisplayed: 10µF  [1206]  (hidden comment: GRM31CR71E106KA12L)
C103  ValueDisplayed: 10µF  [1206]  (hidden comment: GRM31CR71E106KA12L)
C104  ValueDisplayed: 10µF  [1206]  (hidden comment: GRM31CR71E106KA12L)
C105  ValueDisplayed: 10µF  [1206]  (hidden comment: GRM31CR71E106KA12L)
C106  ValueDisplayed: 3300pF  [0402]  (hidden comment: C1005X7R1H332K)
C110  ValueDisplayed: 0.1µF  [0603]  (hidden comment: C0603C104J3RACTU)
C111  ValueDisplayed: 10µF  [0603]  (hidden comment: C0603C106M9PACTU)
C112  ValueDisplayed: 0.1µF  [0402]  (hidden comment: GRM155R61C104KA88D)
C113  ValueDisplayed: 1500pF  [0805_HV]  (hidden comment: 08051C152KAT2A)
C200  ValueDisplayed: 1000pF  [0402]  (hidden comment: C1005C0G1E102J)
C201  ValueDisplayed: 10µF  [1206]  (hidden comment: GRM31CR71E106KA12L)
C202  ValueDisplayed: 10µF  [1206]  (hidden comment: GRM31CR71E106KA12L)
C203  ValueDisplayed: 10µF  [1206]  (hidden comment: GRM31CR71E106KA12L)
C204  ValueDisplayed: 10µF  [1206]  (hidden comment: GRM31CR71E106KA12L)
C205  ValueDisplayed: 10µF  [1206]  (hidden comment: GRM31CR71E106KA12L)
C206  ValueDisplayed: 3300pF  [0402]  (hidden comment: C1005X7R1H332K)
C210  ValueDisplayed: 0.1µF  [0603]  (hidden comment: C0603C104J3RACTU)
C211  ValueDisplayed: 10µF  [0603]  (hidden comment: C0603C106M9PACTU)
C212  ValueDisplayed: 0.1µF  [0402]  (hidden comment: GRM155R61C104KA88D)
C213  ValueDisplayed: 1500pF  [0805_HV]  (hidden comment: 08051C152KAT2A)
C300  ValueDisplayed: 1000pF  [0402]  (hidden comment: C1005C0G1E102J)
C301  ValueDisplayed: 10µF  [1206]  (hidden comment: GRM31CR71E106KA12L)
C302  ValueDisplayed: 10µF  [1206]  (hidden comment: GRM31CR71E106KA12L)
C303  ValueDisplayed: 10µF  [1206]  (hidden comment: GRM31CR71E106KA12L)
C304  ValueDisplayed: 10µF  [1206]  (hidden comment: GRM31CR71E106KA12L)
C305  ValueDisplayed: 10µF  [1206]  (hidden comment: GRM31CR71E106KA12L)
C306  ValueDisplayed: 3300pF  [0402]  (hidden comment: C1005X7R1H332K)
C310  ValueDisplayed: 0.1µF  [0603]  (hidden comment: C0603C104J3RACTU)
C311  ValueDisplayed: 10µF  [0603]  (hidden comment: C0603C106M9PACTU)
C312  ValueDisplayed: 0.1µF  [0402]  (hidden comment: GRM155R61C104KA88D)
C313  ValueDisplayed: 1500pF  [0805_HV]  (hidden comment: 08051C152KAT2A)
L100  FP1308R3-R21  value 210 uH  [IND_IHLP2525/5050]
L200  FP1308R3-R21  value 210 uH  [IND_IHLP2525/5050]
L300  FP1308R3-R21  value 210 uH  [IND_IHLP2525/5050]
R100  value 0  [0402]  (hidden comment: RC0402JR-070RL)
R110  value 2.2  [0402]  (hidden comment: CRCW04022R20JNED)
R113  value 1.0  [1206]  (hidden comment: CRM1206-JW-1R0ELF)
R200  value 0  [0402]  (hidden comment: RC0402JR-070RL)
R210  value 2.2  [0402]  (hidden comment: CRCW04022R20JNED)
R213  value 1.0  [1206]  (hidden comment: CRM1206-JW-1R0ELF)
R300  value 0  [0402]  (hidden comment: RC0402JR-070RL)
R310  value 2.2  [0402]  (hidden comment: CRCW04022R20JNED)
R313  value 1.0  [1206]  (hidden comment: CRM1206-JW-1R0ELF)
TP100  5015  [Testpoint_Keystone_Miniature]  (value not drawn)
TP200  5015  [Testpoint_Keystone_Miniature]  (value not drawn)
TP300  5015  [Testpoint_Keystone_Miniature]  (value not drawn)
TP301  TP_5016_SM  [TP_5016_SM]
U100  CSD95378BQ5M  [DQP0012A]
U200  CSD95378BQ5M  [DQP0012A]
U300  CSD95378BQ5M  [DQP0012A]

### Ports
CSP1 (out), CSP2 (out), CSP3 (out), FCCM, PWM1 (in), PWM2 (in), PWM3 (in), REFIN1, REFIN2, REFIN3, TSEN

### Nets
5V: C111.1 C211.1 C311.1 U100.3(ENABLE) U100.5(VDD) U200.3(ENABLE) U200.5(VDD) U300.3(ENABLE) U300.5(VDD)
GND: C100.1 C101.2 C102.2 C103.2 C104.2 C105.2 C106.2 C111.2 C112.2 C200.1 C201.2 C202.2 C203.2 C204.2 C205.2 C206.2 C211.2 C212.2 C300.1 C301.2 C302.2 C303.2 C304.2 C305.2 C306.2 C311.2 C312.2 R113.1 R213.1 R313.1 TP301.1 U100.4(PGND) U100.13(PGND) U200.4(PGND) U200.13(PGND) U300.4(PGND) U300.13(PGND)
Vin: C101.1 C102.1 C103.1 C104.1 C105.1 C106.1 C201.1 C202.1 C203.1 C204.1 C205.1 C206.1 C301.1 C302.1 C303.1 C304.1 C305.1 C306.1 U100.7(VIN) U200.7(VIN) U300.7(VIN)
VOUT: L100.2 L200.2 L300.2
CSP1: U100.1(IOUT) ; port CSP1
CSP2: U200.1(IOUT) ; port CSP2
CSP3: U300.1(IOUT) ; port CSP3
FCCM: R100.1 R200.1 R300.1 ; port FCCM
PWM1: U100.12(PWM) ; port PWM1
PWM2: U200.12(PWM) ; port PWM2
PWM3: U300.12(PWM) ; port PWM3
REFIN1: C112.1 U100.2(REFIN) ; port REFIN1
REFIN2: C212.1 U200.2(REFIN) ; port REFIN2
REFIN3: C312.1 U300.2(REFIN) ; port REFIN3
TSEN: C100.2 C200.2 C300.2 U100.11(TAO/FAULT) U200.11(TAO/FAULT) U300.11(TAO/FAULT) ; port TSEN
NetC110_1: C110.1 R110.1
NetC110_2: C110.2 U100.9(BOOT)
NetC113_1: C113.1 L100.1 TP100.1 U100.6(VSW)
NetC113_2: C113.2 R113.2
NetC210_1: C210.1 R210.1
NetC210_2: C210.2 U200.9(BOOT)
NetC213_1: C213.1 L200.1 TP200.1 U200.6(VSW)
NetC213_2: C213.2 R213.2
NetC310_1: C310.1 R310.1
NetC310_2: C310.2 U300.9(BOOT)
NetC313_1: C313.1 L300.1 TP300.1 U300.6(VSW)
NetC313_2: C313.2 R313.2
NetR100_2: R100.2 U100.10(FCCM)
NetR110_2: R110.2 U100.8(BOOT_R)
NetR200_2: R200.2 U200.10(FCCM)
NetR210_2: R210.2 U200.8(BOOT_R)
NetR300_2: R300.2 U300.10(FCCM)
NetR310_2: R310.2 U300.8(BOOT_R)

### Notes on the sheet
- Parts with ref des 4xx, 5xx, 6xx not populated in 3 phase max applications applications
- VIN = 10V to 14V

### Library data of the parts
C100 C200 C300 = C1005C0G1E102J: CAP, CERM, 1000pF, 25V, +/-5%, C0G/NP0, 0402; Manufacturer: TDK; Polarized: N; CompType: Capacitor; U/M: EA; Cap_F: 0.000000001; Tolerance_%: 5; Value1: Unknown; VDC_V: 25; TaMin_C: -55; TaMax_C: 125
C101-C105 C201-C205 C301-C305 = GRM31CR71E106KA12L: CAP, CERM, 10uF, 25V, +/-10%, X7R, 1206; Manufacturer: MuRata; Polarized: N; CompType: Capacitor; U/M: EA; Cap_F: 0.00001; Tolerance_%: 10; Value1: Unknown; VDC_V: 25; TaMin_C: -55; TaMax_C: 125; Cap_Case: 2220
C106 C206 C306 = C1005X7R1H332K: CAP, CERM, 3300pF, 50V, +/-10%, X7R, 0402; Manufacturer: TDK; Polarized: N; CompType: Capacitor; U/M: EA; Cap_F: 0.0000000033; Tolerance_%: 10; ESR_Ohm: 0.12; Value1: 0.12 ohm; VDC_V: 50; TaMin_C: -55; TaMax_C: 125
C110 C210 C310 = C0603C104J3RACTU: CAP, CERM, 0.1uF, 25V, +/-5%, X7R, 0603; Manufacturer: Kemet; Polarized: N; CompType: Capacitor; U/M: EA; Cap_F: 0.0000001; Tolerance_%: 5; Value1: Unknown; VDC_V: 25; TaMin_C: -55; TaMax_C: 125
C111 C211 C311 = C0603C106M9PACTU: CAP, CERM, 10uF, 6.3V, +/-20%, X5R, 0603; Manufacturer: Kemet; Polarized: N; CompType: Capacitor; U/M: EA; Cap_F: 0.00001; Tolerance_%: 20; ESR_Ohm: 0.004; Value1: 0.004 ohm; VDC_V: 6.3; IRMS_A: 8.9; TaMin_C: -55; TaMax_C: 85
C112 C212 C312 = GRM155R61C104KA88D: CAP, CERM, 0.1uF, 16V, +/-10%, X5R, 0402; Manufacturer: MuRata; Polarized: N; CompType: Capacitor; U/M: EA; Cap_F: 0.0000001; Tolerance_%: 10; Value1: Unknown; VDC_V: 16; TaMin_C: -55; TaMax_C: 85
C113 C213 C313 = 08051C152KAT2A: CAP, CERM, 1500pF, 100V, +/-10%, X7R, 0805; Manufacturer: AVX; Polarized: N; CompType: Capacitor; U/M: EA; Cap_F: 0.0000000015; Tolerance_%: 10; ESR_Ohm: 0.229; Value1: 0.229 ohm; VDC_V: 100; TaMin_C: -55; TaMax_C: 125; Cap_Case: 0805
L100 L200 L300 = IND_IHLP-2525/5050: Inductor, Low-Profile, High-Current ±20%; Manufacturer: Cooper Bussman; Area: 307800
R100 R200 R300 = RC0402JR-070RL: RES, 0 ohm, 5%, 0.063W, 0402; Manufacturer: Yageo America; CompType: Resistor; Value_Code: 0000; Tolerance_%: 5; Power_W: 0.063; VDC_V: 50; TempCo: 200 ppm/C; EIA_Code: E24; U/M: EA
R110 R210 R310 = CRCW04022R20JNED: RES, 2.2 ohm, 5%, 0.063W, 0402; Manufacturer: Vishay-Dale; CompType: Resistor; Value_Code: 2R20; Tolerance_%: 5; Power_W: 0.063; VDC_V: 50; TempCo: 200 ppm/C; EIA_Code: E24; U/M: EA
R113 R213 R313 = CRM1206-JW-1R0ELF: RES, 1.0 ohm, 5%, 0.5W, 1206; Manufacturer: Bourns; CompType: Resistor; Res_ohm: 1; Value_Code: 1R00; Tolerance_%: 5; Power_W: 0.5; TempCo: 150 ppm/C; EIA_Code: E24; U/M: EA
TP100 TP200 TP300 = 5015: Test Point, Miniature, SMT; Manufacturer: Keystone; CompType: Test Point Loop; U/M: EA
TP301 = TP_5016_SM: Test Point, SM, 0.150 x 0.090; Manufacturer: Keystone; PartNumber: 5016; Value: 5016
U100 U200 U300 = CSD95378BQ5M: Synchronous Buck NexFET Power Stage, DQP0012A; Alternate Manufacturer: None; Manufacturer: Texas Instruments; SymbolCreator: a0411947; CompType: IC; U/M: EA

## Sheet Hardware_PMP10306A.SchDoc
size 431 x 279 mm; Date: Not shown in title block; ApprovedBy: Not shown in title block; CheckedBy: Not shown in title block; Author: Not shown in title block; CompanyName: Not shown in title block; Engineer: Not shown in title block; Organization: Not shown in title block; Address1: Not shown in title block; Address2: Not shown in title block; Address3: Not shown in title block; Address4: Not shown in title block; DocumentNumber: 5; Revision: Use project parameter SCH_Rev; SheetNumber: 5; SheetTotal: 5; PageSetup: Record=PageOptions|CenterHorizontal=True|CenterVertical=True|PrintScale=1.00|XCorrection=1.00|YCorrection=1.00|PrintKind=0|BorderSize=5000000|LeftOffset=0|BottomOffset=0|Orientation=2|PaperLength=1000|PaperWidth=1000|Scale=100|PaperSource=15|PrintQuality=600|MediaType=1|DitherType=10|PaperKind=Letter|PrintScaleMode=1
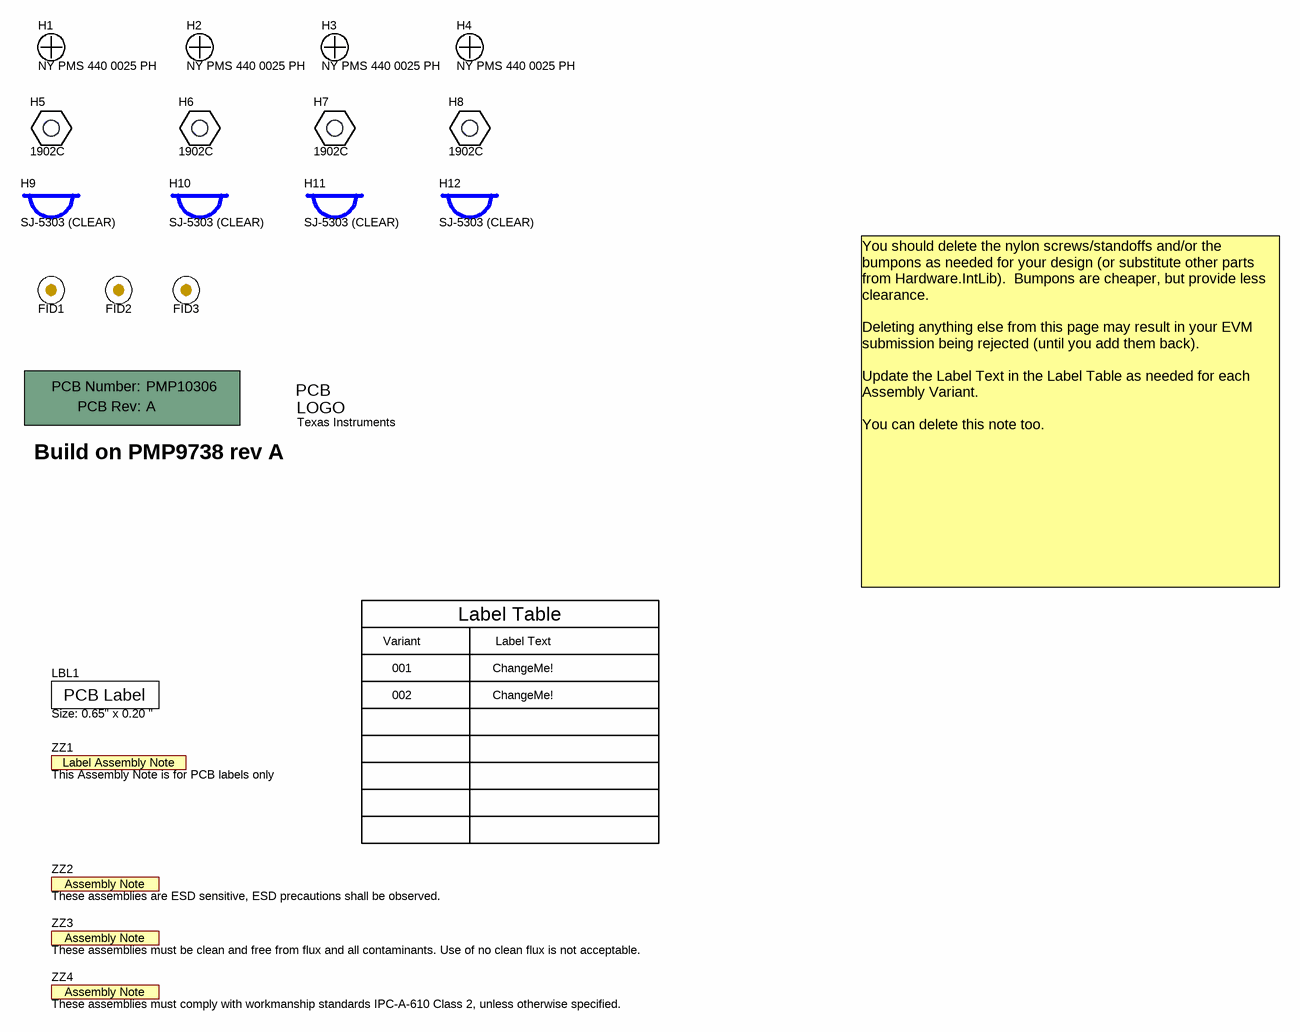
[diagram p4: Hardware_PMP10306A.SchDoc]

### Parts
!PCB  Printed Circuit Board  (value not drawn)  (mechanical)
FID1  Fiducial  [Fiducial10-20]  (value not drawn)
FID2  Fiducial  [Fiducial10-20]  (value not drawn)
FID3  Fiducial  [Fiducial10-20]  (value not drawn)
H1  NY PMS 440 0025 PH  [NY PMS 440 0025 PH]
H2  NY PMS 440 0025 PH  [NY PMS 440 0025 PH]
H3  NY PMS 440 0025 PH  [NY PMS 440 0025 PH]
H4  NY PMS 440 0025 PH  [NY PMS 440 0025 PH]
H5  1902C  [Keystone_1902C]
H6  1902C  [Keystone_1902C]
H7  1902C  [Keystone_1902C]
H8  1902C  [Keystone_1902C]
H9  SJ-5303 (CLEAR)  [Bumpon_SJ5003Transparent]
H10  SJ-5303 (CLEAR)  [Bumpon_SJ5003Transparent]
H11  SJ-5303 (CLEAR)  [Bumpon_SJ5003Transparent]
H12  SJ-5303 (CLEAR)  [Bumpon_SJ5003Transparent]
LBL1  Size: 0.65" x 0.20 "  [Label_650x200]
Logo1  Texas Instruments  [TI_Stacked_SolderMask_Small]  (no BOM)
ZZ1  This Assembly Note is for PCB labels only  [AssemblyNoteLabel]  (no BOM)
ZZ2  These assemblies are ESD sensitive, ESD precautions shall be observed.  [AssemblyNote]  (no BOM)
ZZ3  These assemblies must be clean and free from flux and all contaminants. Use of no clean flux is not acceptable.  [AssemblyNote]  (no BOM)
ZZ4  These assemblies must comply with workmanship standards IPC-A-610 Class 2, unless otherwise specified.  [AssemblyNote]  (no BOM)

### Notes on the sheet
- Build on PMP9738 rev A
- Variant
- Label Table
- Label Text
- You should delete the nylon screws/standoffs and/or the bumpons as needed for your design (or substitute other parts from Hardware.IntLib).  Bumpons are cheaper, but provide less clearance.
  Deleting anything else from this page may result in your EVM submission being rejected (until you add them back).
  Update the Label Text in the Label Table as needed for each Assembly Variant.
  You can delete this note too.
- 001
- 002
- ChangeMe!

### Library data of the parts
!PCB = PCB: Manufacturer: Any; PartNumber: PMP9738A; SymbolCreator: a0412235
FID1-FID3 = Fiducial: Fiducial mark.  There is nothing to buy or mount.; SymbolCreator: codlsc
H1-H4 = NY PMS 440 0025 PH: Machine Screw, Round, #4-40 x 1/4, Nylon, Philips panhead; Manufacturer: B&F Fastener Supply; CompType: Hardware; SymbolCreator: codlsc; U/M: EA
H5-H8 = 1902C: Standoff, Hex, 0.5"L #4-40 Nylon; Manufacturer: Keystone; CompType: Hardware
H9-H12 = SJ-5303 (CLEAR): Bumpon, Hemisphere, 0.44 X 0.20, Clear; Manufacturer: 3M; SymbolCreator: a0412235
LBL1 = THT-14-423-10: as LBL41 on sheet Control_TPS53631
Logo1 = TI_Logo: Texas Instrument Corporate Signature; SymbolCreator: codlsc
ZZ1 = AssemblyNoteLabel: SymbolCreator: a0412235
ZZ2-ZZ4 = AssemblyNote: SymbolCreator: codlsc

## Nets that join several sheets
5V: Input_Bias_dynLoad (12 pins), Control_TPS53631 (C43.2 R73.2 U42.1 U42.3), PowerTrains (9 pins)
GND: Input_Bias_dynLoad (55 pins), Control_TPS53631 (26 pins), PowerTrains (37 pins)
Vin: Input_Bias_dynLoad (14 pins), Control_TPS53631 (R72.2), PowerTrains (21 pins)
VOUT: Input_Bias_dynLoad (25 pins), PowerTrains (L100.2 L200.2 L300.2)
CSP1: Control_TPS53631 (U41.3), PowerTrains (U100.1)
CSP2: Control_TPS53631 (J42.9 U41.4), PowerTrains (U200.1)
CSP3: Control_TPS53631 (J42.7 U41.5), PowerTrains (U300.1)
FCCM: Control_TPS53631 (J47.1 R64.2), PowerTrains (R100.1 R200.1 R300.1)
PWM1: Control_TPS53631 (U41.38), PowerTrains (U100.12)
PWM2: Control_TPS53631 (U41.37), PowerTrains (U200.12)
PWM3: Control_TPS53631 (U41.36), PowerTrains (U300.12)
REFIN1: Control_TPS53631 (R81.2), PowerTrains (C112.1 U100.2)
REFIN2: Control_TPS53631 (R82.2), PowerTrains (C212.1 U200.2)
REFIN3: Control_TPS53631 (R83.2), PowerTrains (C312.1 U300.2)
TSEN: Control_TPS53631 (C52.1 R70.2 U41.40), PowerTrains (6 pins)
VSN: Input_Bias_dynLoad (J4.1 R16.1), Control_TPS53631 (C42.2 U41.10)
VSP: Input_Bias_dynLoad (J4.2 R15.1), Control_TPS53631 (C42.1 U41.9)

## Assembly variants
001: not fitted FID1 FID2 FID3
